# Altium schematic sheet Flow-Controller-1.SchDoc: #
size A3; ApprovedBy: #; DrawnBy: #; DocumentNumber: #; Revision: #; SheetNumber: 1; SheetTotal: 2; DocumentRevision: #; Reviewed: #; QA: #; CM: #; ECR: #; PageSetup: Record=PageOptions¦CenterHorizontal=True¦CenterVertical=True¦PrintScale=0.97¦XCorrection=1.00¦YCorrection=1.00¦PrintKind=1¦BorderSize=5000000¦LeftOffset=0¦BottomOffset=0¦Orientation=2¦PaperLength=1000¦PaperWidth=1000¦Scale=100¦PaperSource=7¦PrintQuality=-4¦MediaType=1¦DitherType=10¦PaperKind=A3¦PrintScaleMode=1
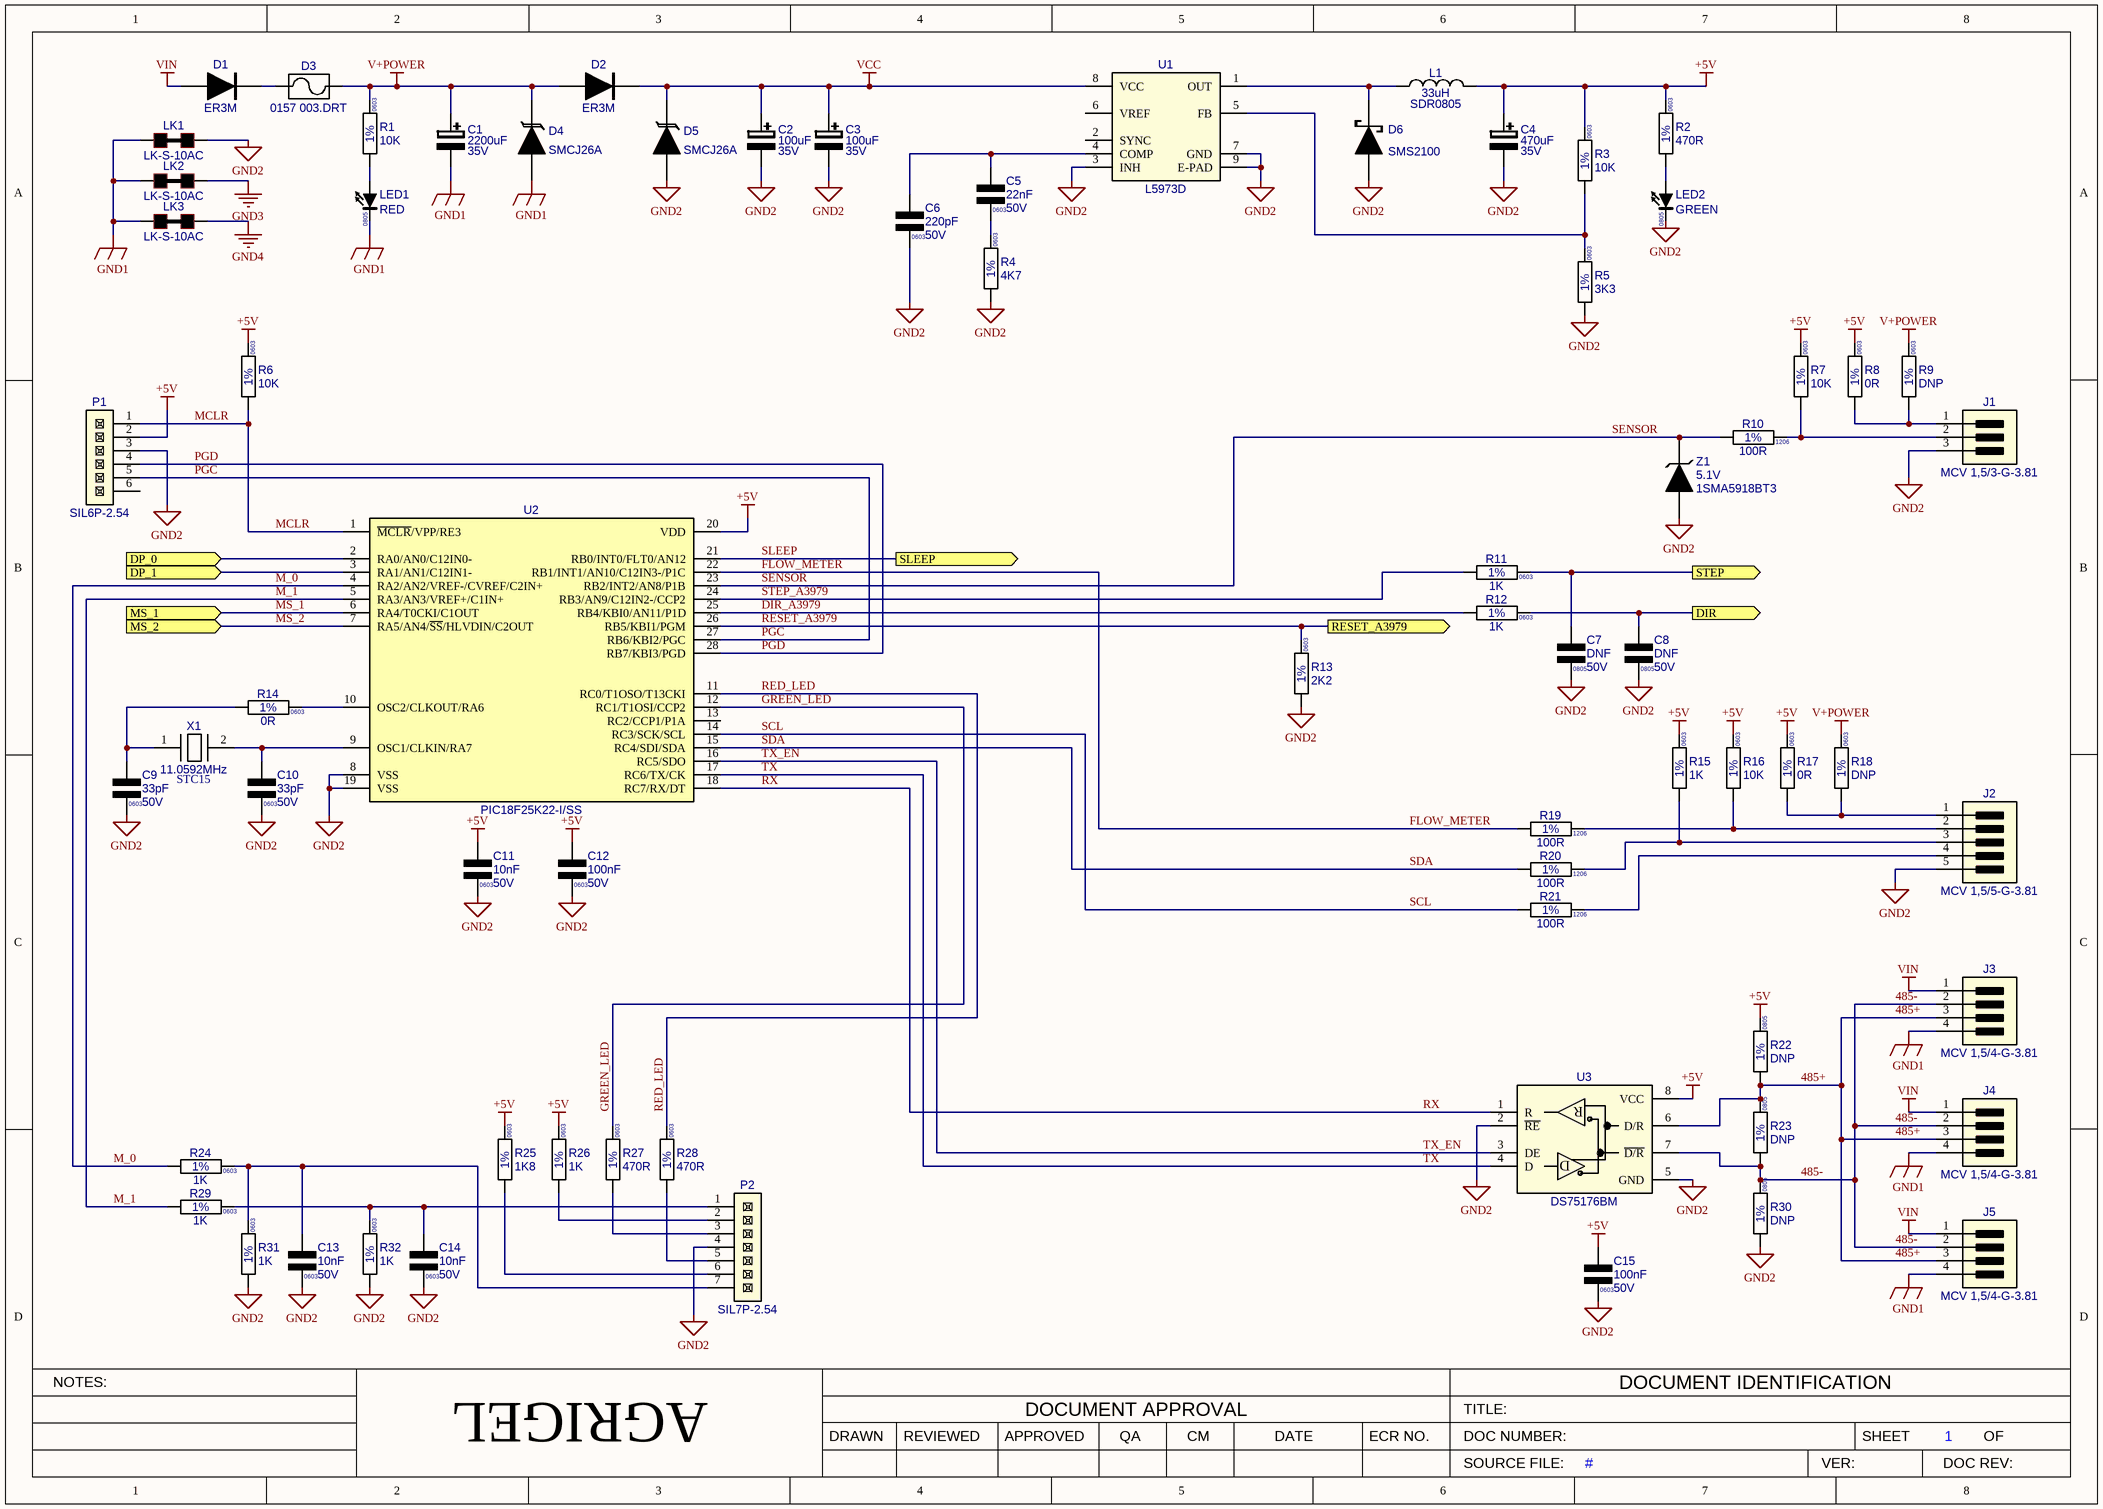
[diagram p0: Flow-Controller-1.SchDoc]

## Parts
C1  value 2200uF  Voltage: 35V  [EL-RAD-16X31.5]  (hidden comment: CAP-EL_2200uF_35V_20%-YXF)
C2  value 100uF  Voltage: 35V  [CAP-EL-SMD-10x10.5]  (hidden comment: 100uF35V-20%-EEVFC)
C3  value 100uF  Voltage: 35V  [CAP-EL-SMD-10x10.5]  (hidden comment: 100uF35V-20%-EEVFC)
C4  value 470uF  Voltage: 35V  [CAP-EL-SMD-10x10.5]  (hidden comment: 470uF-35V-20%-LZ)
C5  value 22nF  Voltage: 50V  Text1: 0603  [CAPC0603X85N]  (hidden comment: 22nF_C0603_50V_10%_X7R)
C6  value 220pF  Voltage: 50V  Text1: 0603  [CAPC0603X85N]  (hidden comment: 220pF_C0603_50V_10%_NP0)
C7  value DNF  Voltage: 50V  Text1: 0805  [CAPC0805X110N]  (hidden comment: DNF_C0805_50V_10%_X7R)
C8  value DNF  Voltage: 50V  Text1: 0805  [CAPC0805X110N]  (hidden comment: DNF_C0805_50V_10%_X7R)
C9  value 33pF  Voltage: 50V  Text1: 0603  [CAPC0603X85N]  (hidden comment: 33pF_C0603_50V_10%_NP0)
C10  value 33pF  Voltage: 50V  Text1: 0603  [CAPC0603X85N]  (hidden comment: 33pF_C0603_50V_10%_NP0)
C11  value 10nF  Voltage: 50V  Text1: 0603  [CAPC0603X85N]  (hidden comment: 10nF_C0603_50V_10%_X7R)
C12  value 100nF  Voltage: 50V  Text1: 0603  [CAPC0603X85N]  (hidden comment: 100nF_C0603_50V_10%_X7R)
C13  value 10nF  Voltage: 50V  Text1: 0603  [CAPC0603X85N]  (hidden comment: 10nF_C0603_50V_10%_X7R)
C14  value 10nF  Voltage: 50V  Text1: 0603  [CAPC0603X85N]  (hidden comment: 10nF_C0603_50V_10%_X7R)
C15  value 100nF  Voltage: 50V  Text1: 0603  [CAPC0603X85N]  (hidden comment: 100nF_C0603_50V_10%_X7R)
D1  ER3M  [SMC]
D2  ER3M  [SMC]
D3  Text1: 0157 003.DRT  [LF-0157]  (hidden comment: 0157003.DRT)
D4  SMCJ26A  [SMC]
D5  SMCJ26A  [SMC]
D6  SMS2100  [DO-213AB]
J1  MCV 1,5/3-G-3.81  [ECH381V-03P]
J2  MCV 1,5/5-G-3.81  [ECH381V-05P]
J3  MCV 1,5/4-G-3.81  [ECH381V-04P]
J4  MCV 1,5/4-G-3.81  [ECH381V-04P]
J5  MCV 1,5/4-G-3.81  [ECH381V-04P]
L1  value 33uH  [SDR0805]  (hidden comment: SDR0805-330K)
LED1  value RED  Text2: 0805  [LED0805-Red]  (hidden comment: RED_0805_SMD)
LED2  value GREEN  Text2: 0805  [LED0805-Green]  (hidden comment: GREEN_0805_SMD)
LK1  Part Number: LK-S-10AC  [SLINK-10A-C]  (hidden comment: Link-SMD-10A-Closed)  (no BOM)
LK2  Part Number: LK-S-10AC  [SLINK-10A-C]  (hidden comment: Link-SMD-10A-Closed)  (no BOM)
LK3  Part Number: LK-S-10AC  [SLINK-10A-C]  (hidden comment: Link-SMD-10A-Closed)  (no BOM)
P1  SIL6P-2.54  [SIL6P-2.54]
P2  SIL7P-2.54  [SIL7P-2.54]
R1  value 10K  Tol: 1%  Text1: 0603  [RESC0603X60N]  (hidden comment: 10K_R0603_1%)
R2  value 470R  Tol: 1%  Text1: 0603  [RESC0603X60N]  (hidden comment: 470R_R0603_1%)
R3  value 10K  Tol: 1%  Text1: 0603  [RESC0603X60N]  (hidden comment: 10K_R0603_1%)
R4  value 4K7  Tol: 1%  Text1: 0603  [RESC0603X60N]  (hidden comment: 4K7_R0603_1%)
R5  value 3K3  Tol: 1%  Text1: 0603  [RESC0603X60N]  (hidden comment: 3K3_R0603_1%)
R6  value 10K  Tol: 1%  Text1: 0603  [RESC0603X60N]  (hidden comment: 10K_R0603_1%)
R7  value 10K  Tol: 1%  Text1: 0603  [RESC0603X60N]  (hidden comment: 10K_R0603_1%)
R8  value 0R  Tol: 1%  Text1: 0603  [RESC0603X60N]  (hidden comment: 0R_R0603_1%)
R9  value DNP  Tol: 1%  Text1: 0603  [RESC0603X60N]  (hidden comment: DNP_R0603_1%)
R10  value 100R  Tol: 1%  Text1: 1206  [RESC1206X71N]  (hidden comment: 100R_R1206_1%)
R11  value 1K  Tol: 1%  Text1: 0603  [RESC0603X60N]  (hidden comment: 1K_R0603_1%)
R12  value 1K  Tol: 1%  Text1: 0603  [RESC0603X60N]  (hidden comment: 1K_R0603_1%)
R13  value 2K2  Tol: 1%  Text1: 0603  [RESC0603X60N]  (hidden comment: 2K2_R0603_1%)
R14  value 0R  Tol: 1%  Text1: 0603  [RESC0603X60N]  (hidden comment: 0R_R0603_1%)
R15  value 1K  Tol: 1%  Text1: 0603  [RESC0603X60N]  (hidden comment: 1K_R0603_1%)
R16  value 10K  Tol: 1%  Text1: 0603  [RESC0603X60N]  (hidden comment: 10K_R0603_1%)
R17  value 0R  Tol: 1%  Text1: 0603  [RESC0603X60N]  (hidden comment: 0R_R0603_1%)
R18  value DNP  Tol: 1%  Text1: 0603  [RESC0603X60N]  (hidden comment: DNP_R0603_1%)
R19  value 100R  Tol: 1%  Text1: 1206  [RESC1206X71N]  (hidden comment: 100R_R1206_1%)
R20  value 100R  Tol: 1%  Text1: 1206  [RESC1206X71N]  (hidden comment: 100R_R1206_1%)
R21  value 100R  Tol: 1%  Text1: 1206  [RESC1206X71N]  (hidden comment: 100R_R1206_1%)
R22  value DNP  Tol: 1%  Text1: 0805  [RESC0805X65N]  (hidden comment: DNP_R0805_1%)
R23  value DNP  Tol: 1%  Text1: 0805  [RESC0805X65N]  (hidden comment: DNP_R0805_1%)
R24  value 1K  Tol: 1%  Text1: 0603  [RESC0603X60N]  (hidden comment: 1K_R0603_1%)
R25  value 1K8  Tol: 1%  Text1: 0603  [RESC0603X60N]  (hidden comment: 1K8_R0603_1%)
R26  value 1K  Tol: 1%  Text1: 0603  [RESC0603X60N]  (hidden comment: 1K_R0603_1%)
R27  value 470R  Tol: 1%  Text1: 0603  [RESC0603X60N]  (hidden comment: 470R_R0603_1%)
R28  value 470R  Tol: 1%  Text1: 0603  [RESC0603X60N]  (hidden comment: 470R_R0603_1%)
R29  value 1K  Tol: 1%  Text1: 0603  [RESC0603X60N]  (hidden comment: 1K_R0603_1%)
R30  value DNP  Tol: 1%  Text1: 0805  [RESC0805X65N]  (hidden comment: DNP_R0805_1%)
R31  value 1K  Tol: 1%  Text1: 0603  [RESC0603X60N]  (hidden comment: 1K_R0603_1%)
R32  value 1K  Tol: 1%  Text1: 0603  [RESC0603X60N]  (hidden comment: 1K_R0603_1%)
U1  Part Number: L5973D  [HSOP8]  (hidden comment: L5973D-HSOP8)
U2  PIC18F25K22-I/SS  [SSOP28]
U3  DS75176BM  [SO8]
X1  Text2: STC15  Text1: 11.0592MHz  [XT-HEX15]  (hidden comment: XTAL_11.0592MHz_STCX15)
Z1  value 5.1V  [SMA]  (hidden comment: 1SMA5918BT3)

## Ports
DIR, DP_0, DP_1, MS_1, MS_2, RESET_A3979, SLEEP, STEP

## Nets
+5V: C4.1 C11.1 C12.1 C15.1 L1.2 P1.2 R2.1 R3.1 R6.1 R7.1 R8.1 R15.1 R16.1 R17.1 R22.1 R25.1 R26.1 U2.20(VDD) U3.8(VCC)
GND1: C1.2 D4.2(A) J3.4 J4.4 J5.4 LED1.1(K) LK1.1 LK2.1 LK3.1
GND2: C2.2 C3.2 C4.2 C6.2 C7.2 C8.2 C9.2 C10.2 C11.2 C12.2 C13.2 C14.2 C15.2 D5.2(A) D6.2(A) J1.3 J2.5 LED2.1(K) LK1.2 P1.3 P2.4 R4.2 R5.2 R13.2 R30.2 R31.2 R32.2 U1.3(INH) U1.7(GND) U1.9(E-PAD) U2.8(VSS) U2.19(VSS) U3.2(~{RE}) U3.5(GND) Z1.2(A)
GND3: LK2.2
GND4: LK3.2
V+POWER: C1.1 D2.2(A) D3.2 D4.1(C) R1.1 R9.1 R18.1
VCC: C2.1 C3.1 D2.1(C) D5.1(C) U1.8(VCC)
VIN: D1.2(A) J3.1 J4.1 J5.1
485+: J3.3 J4.3 J5.3 R22.2 R23.1 U3.6(D/R)
485-: J3.2 J4.2 J5.2 R23.2 R30.1 U3.7(~{D/R})
DIR: C8.1 R12.2 ; port DIR
DIR_A3979: R12.1 U2.25(RB4/KBI0/AN11/P1D)
DP_0: U2.2(RA0/AN0/C12IN0-) ; port DP_0
DP_1: U2.3(RA1/AN1/C12IN1-) ; port DP_1
FLOW_METER: R19.1 U2.22(RB1/INT1/AN10/C12IN3-/P1C)
GREEN_LED: R27.1 U2.12(RC1/T1OSI/CCP2)
M_0: R24.1 U2.4(RA2/AN2/VREF-/CVREF/C2IN+)
M_1: R29.1 U2.5(RA3/AN3/VREF+/C1IN+)
MCLR: P1.1 R6.2 U2.1(~{MCLR}/VPP/RE3)
MS_1: U2.6(RA4/T0CKI/C1OUT) ; port MS_1
MS_2: U2.7(RA5/AN4/~{SS}/HLVDIN/C2OUT) ; port MS_2
PGC: P1.5 U2.27(RB6/KBI2/PGC)
PGD: P1.4 U2.28(RB7/KBI3/PGD)
RED_LED: R28.1 U2.11(RC0/T1OSO/T13CKI)
RESET_A3979: R13.1 U2.26(RB5/KBI1/PGM) ; port RESET_A3979
RX: U2.18(RC7/RX/DT) U3.1(R)
SCL: R21.1 U2.14(RC3/SCK/SCL)
SDA: R20.1 U2.15(RC4/SDI/SDA)
SENSOR: R10.1 U2.23(RB2/INT2/AN8/P1B) Z1.1(C)
SLEEP: U2.21(RB0/INT0/FLT0/AN12) ; port SLEEP
STEP: C7.1 R11.2 ; port STEP
STEP_A3979: R11.1 U2.24(RB3/AN9/C12IN2-/CCP2)
TX: U2.17(RC6/TX/CK) U3.4(D)
TX_EN: U2.16(RC5/SDO) U3.3(DE)
NetC5_1: C5.1 C6.1 U1.4(COMP)
NetC5_2: C5.2 R4.1
NetC9_1: C9.1 R14.1 X1.1
NetC10_1: C10.1 U2.9(OSC1/CLKIN/RA7) X1.2
NetC13_1: C13.1 P2.7 R24.2 R31.1
NetC14_1: C14.1 P2.1 R29.2 R32.1
NetD1_1: D1.1(C) D3.1
NetD6_1: D6.1(C) L1.1 U1.1(OUT)
NetJ1_1: J1.1 R8.2 R9.2
NetJ1_2: J1.2 R7.2 R10.2
NetJ2_1: J2.1 R17.2 R18.2
NetJ2_2: J2.2 R16.2 R19.2
NetJ2_3: J2.3 R15.2 R20.2
NetJ2_4: J2.4 R21.2
NetLED1_2: LED1.2(A) R1.2
NetLED2_2: LED2.2(A) R2.2
NetP2_2: P2.2 R26.2
NetP2_3: P2.3 R27.2
NetP2_5: P2.5 R28.2
NetP2_6: P2.6 R25.2
NetR3_2: R3.2 R5.1 U1.5(FB)
NetR14_2: R14.2 U2.10(OSC2/CLKOUT/RA6)

Not connected (* = marked no-connect by the designer): P1 6; U1 2(SYNC) 6(VREF); U2 13(RC2/CCP1/P1A)

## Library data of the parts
C1 = 2200uF_35V_20%_V-YXF: Cap Electrolytic THP Radial - Low Imp; Manufacturer: Rubycon; Part Number: 35YXF2200M; Tol: 20%
C2 C3 = 100uF-35V-20%-EEVFC_V: Cap Electrolytic SMD Low Imp; Manufacturer: Panasonic; Part Number: EEVFC1V101P; Tol: 20%
C4 = 470uF-35V-20%-LZ_V: Cap Electrolytic SMD Low Imp; Manufacturer: KJ Electronics; Part Number: 35LZ471MLC10×10.5EC; Tol: 20%
C5 = 22nF_0603N_50V_10%_X7R_V: Cap Ceramic X7R; Manufacturer: Various; Part Number: 22nF 0603 50V 10% X7R; Board Tech: SMD; Tol: 10%
C6 = 220pF_0603N_50V_10%_NP0_V: Cap Ceramic NP0; Manufacturer: Various; Part Number: 220pF 0603 50V 10% NP0; Board Tech: SMD; Tol: 10%
C7 C8 = DNF_0805N_50V_10%_X7R_V: Do not Fit - Cap Ceramic X7R; Manufacturer: Various; Board Tech: SMD; Tol: 10%
C9 C10 = 33pF_0603N_50V_10%_NP0_V: Cap Ceramic NP0; Manufacturer: Various; Part Number: 33pF 0603 50V 10% NP0; Board Tech: SMD; Tol: 10%
C11 C13 C14 = 10nF_0603N_50V_10%_X7R_V: Cap Ceramic X7R; Manufacturer: Various; Part Number: 10nF 0603 50V 10% X7R; Board Tech: SMD; Tol: 10%; Reutech PN: 5910-CA-0402
C12 C15 = 100nF_0603N_50V_10%_X7R_V: Cap Ceramic X7R; Manufacturer: Various; Part Number: 100nF 0603 50V 10% X7R; Board Tech: SMD; Tol: 10%
D1 D2 = ER3M_SMC_H: Diode Rectifier (1000V 3A); Manufacturer: Diotec; Board Tech: SMD
D3 = FUSE_0157003.DRT_3.0AMP: Fuse Clip and Nano Fuse; Manufacturer: Littelfuse; Board Tech: SMD; Value: 3.0A
D4 D5 = SMCJ26A_V: TVS 1500W SMC; Manufacturer: Various; Board Tech: SMD
D6 = SMS2100_V: Diode Schottky Rectifier 2Amp 100V; Manufacturer: Diotec; Board Tech: SMD; EDM-PN: DIO15
J1 = MCV 1,5/3-G-3.81: Header Pluggable 3.81mm Vertical; Manufacturer: Phoenix; Board Tech: THP
J2 = MCV 1,5/5-G-3.81: Header Pluggable 3.81mm Vertical; Manufacturer: Phoenix; Board Tech: THP
J3-J5 = MCV 1,5/4-G-3.81: Header Pluggable 3.81mm Vertical; Manufacturer: Phoenix; Board Tech: THP
L1 = 33uH_SDR0805_H: Inductor Power; Manufacturer: Bourns; Board Tech: SMD; Tol: 10%
LED1 = RED_0805_SMD_V: LED SMD 0805 Red; Manufacturer: Various; EDM-PN: LED7
LED2 = GREEN_0805_SMD_V: LED SMD 0805 Green; Manufacturer: Various; EDM-PN: LED17
LK1-LK3 = Link-SMD-10A-Closed: Link SMD Closed 10Amp; Manufacturer: Generic
P1 = SIL6P-2.54: Header SIL Male THP, 2.54mm Pitch; Manufacturer: Various
P2 = SIL7P-2.54: Header SIL Male THP, 2.54mm Pitch; Manufacturer: Various
R1 R3 R6 R7 R16 = 10K_0603_V: Resistor Chip SMD; Manufacturer: Various; Part Number: 10K 0603 1%; Watt: 100mW; EDM-PN: RES120
R2 R27 R28 = 470R_0603_V: Resistor Chip SMD; Manufacturer: Various; Part Number: 470R 0603 1%; Watt: 100mW; EDM-PN: RES127
R4 = 4K7_0603_V: Resistor Chip SMD; Manufacturer: Various; Part Number: 4K7 0603 1%; Watt: 100mW
R5 = 3K3_0603_V: Resistor Chip SMD; Manufacturer: Various; Part Number: 3K3 0603 1%; Watt: 100mW
R8 R17 = 0R_0603_V: Resistor Chip SMD; Manufacturer: Various; Part Number: 0R 0603 1%; Watt: 100mW; EDM-PN: RES117
R9 R18 = DNP_0603_V: Resistor Chip SMD; Manufacturer: Various; Watt: 100mW
R10 R19-R21 = 100R_1206_H: Resistor Chip SMD; Manufacturer: Various; Part Number: 100R 1206 1%; Watt: 250mW
R11 R12 R24 R29 = 1K_0603_H: Resistor Chip SMD; Manufacturer: Various; Part Number: 1K 0603 1%; Watt: 100mW
R13 = 2K2_0603_V: Resistor Chip SMD; Manufacturer: Various; Part Number: 2K2 0603 1%; Watt: 100mW; EDM-PN: RES232
R14 = 0R_0603_H: Resistor Chip SMD; Manufacturer: Various; Part Number: 0R 0603 1%; Watt: 100mW; EDM-PN: RES117
R15 R26 R31 R32 = 1K_0603_V: Resistor Chip SMD; Manufacturer: Various; Part Number: 1K 0603 1%; Watt: 100mW
R22 R23 R30 = DNP_0805_V: Resistor Chip SMD; Manufacturer: Various; Watt: 125mW
R25 = 1K8_0603_V: Resistor Chip SMD; Manufacturer: Various; Part Number: 1K8 0603 1%; Watt: 100mW
U1 = L5973D-HSOP8: IC Switching Regulator 2.5A; Manufacturer: ST; Board Tech: SMT
U2 = PIC18F25K22-I/SS_SSOP28: IC Microcontroller 8-Bit; Manufacturer: Microchip; Board Tech: SMD
U3 = DS75176BM_SO8: IC 3.3V RS-485 Drivers and Receivers; Manufacturer: National; Board Tech: SMD
X1 = XTAL_11.0592MHz_STCX15: Crystal - HEX15; Manufacturer: STC; Part Number: STCX15-11.0592MHz; Board Tech: SMD; Value: XTAL_STCX15-11.0592MHz
Z1 = 1SMA5918BT3_X: Zener Diode 1.5W; Manufacturer: On Semi; Board Tech: SMT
